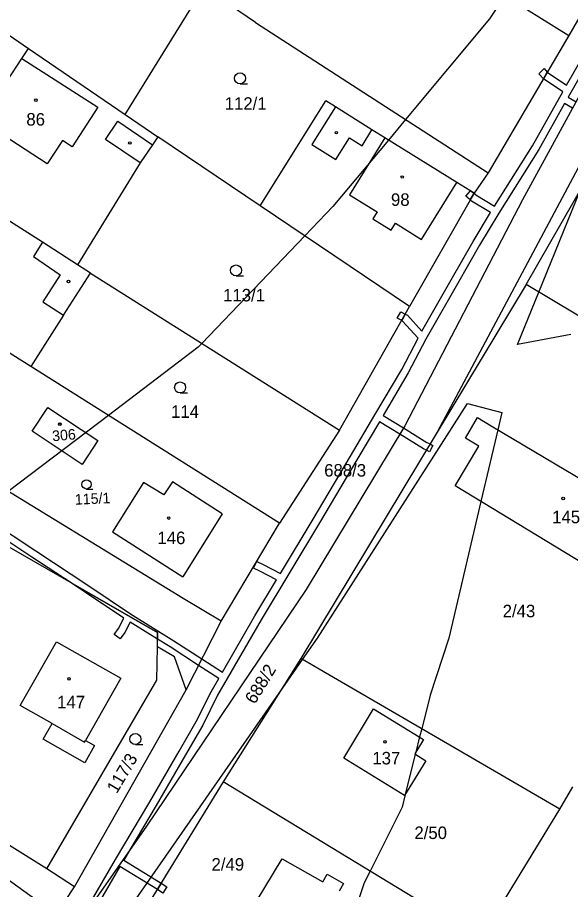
# Model space of a CAD drawing. Extents: x -747333 to -745433, y -1133152 to -1130600.
# Drawn here: x -746266.8 to -746191.7, y -1131861.6 to -1131743.1 of the extents above; entities that cross this region are included whole.
import ezdxf

# ---------------------------------------------------------------- set-up
doc = ezdxf.new("R2010")
doc.units = 0
for name, color, linetype in [('Vrstva 1', 7, 'Continuous'), ('Vrstva 18', 7, 'Continuous'), ('Vrstva 19', 7, 'Continuous'), ('Vrstva 25', 7, 'Continuous'), ('Vrstva 3', 7, 'Continuous'), ('Vrstva 30', 7, 'Continuous'), ('Vrstva 37', 7, 'Continuous'), ('Vrstva 4', 7, 'Continuous'), ('Vrstva 52', 7, 'Continuous'), ('Vrstva 6', 7, 'Continuous')]:
    doc.layers.add(name, color=color, linetype=linetype)

msp = doc.modelspace()

# ---------------------------------------------------------------- linework, layer by layer
at = {"layer": 'Vrstva 1'}
for p, q in [((-746264.81, -1131799.25), (-746262.65, -1131796.05)), ((-746262.65, -1131796.05), (-746255.85, -1131800.56)), ((-746257.99, -1131803.78), (-746264.81, -1131799.25)), ((-746255.85, -1131800.56), (-746257.99, -1131803.78)), ((-746277.66, -1131853.3), (-746261.5, -1131864.88))]:
    msp.add_line(p, q, dxfattribs=at)
for points in [[(-746220.28, -1131727.78), (-746191.89, -1131745.5)], [(-746183.97, -1131731.72), (-746191.89, -1131745.5)], [(-746234.47, -1131743.75), (-746241.4, -1131739.01)], [(-746252.15, -1131756.25), (-746243.25, -1131741.86)], [(-746234.47, -1131743.75), (-746202.88, -1131764.19)], [(-746270.15, -1131743.99), (-746265.3, -1131747.29)], [(-746191.89, -1131745.5), (-746202.88, -1131764.19)], [(-746266.18, -1131748.62), (-746265.3, -1131747.29)], [(-746265.3, -1131747.29), (-746252.15, -1131756.25)], [(-746271.78, -1131757.1), (-746266.18, -1131748.62)], [(-746197.7, -1131779.34), (-746181.5, -1131751.09)], [(-746233.81, -1131768.65), (-746224.93, -1131754.39)], [(-746223.6, -1131755.22), (-746224.93, -1131754.39)], [(-746218.64, -1131758.31), (-746223.6, -1131755.22)], [(-746252.15, -1131756.25), (-746247.71, -1131759.28)], [(-746216.88, -1131759.41), (-746218.64, -1131758.31)], [(-746248.44, -1131760.35), (-746250.13, -1131762.83)], [(-746247.71, -1131759.28), (-746248.44, -1131760.35)], [(-746233.81, -1131768.65), (-746247.71, -1131759.28)], [(-746207.1, -1131765.49), (-746216.88, -1131759.41)], [(-746263.38, -1131773.61), (-746281.7, -1131761.93)], [(-746250.13, -1131762.83), (-746258.62, -1131776.67)], [(-746202.88, -1131764.19), (-746204.77, -1131766.94)], [(-746204.77, -1131766.94), (-746207.1, -1131765.49)], [(-746204.77, -1131766.94), (-746213.53, -1131782.34)], [(-746213.53, -1131782.34), (-746233.81, -1131768.65)], [(-746258.62, -1131776.67), (-746263.38, -1131773.61)], [(-746256.85, -1131777.8), (-746258.62, -1131776.67)], [(-746260.53, -1131783.53), (-746256.85, -1131777.8)], [(-746256.85, -1131777.8), (-746223.05, -1131799.15)], [(-746197.7, -1131779.34), (-746209.77, -1131799.39)], [(-746163.29, -1131799.92), (-746197.7, -1131779.34)], [(-746223.05, -1131799.15), (-746213.53, -1131782.34)], [(-746260.53, -1131783.53), (-746264.99, -1131790.48)], [(-746264.99, -1131790.48), (-746269.53, -1131787.61)], [(-746231.2, -1131811.77), (-746264.99, -1131790.48)], [(-746205.95, -1131800.2), (-746204.31, -1131797.43)], [(-746204.31, -1131797.43), (-746202.46, -1131798.53)], [(-746223.05, -1131799.15), (-746231.2, -1131811.77)], [(-746209.77, -1131799.39), (-746228.3, -1131830.15)], [(-746202.46, -1131798.53), (-746182.41, -1131810.46)], [(-746204.11, -1131801.3), (-746205.95, -1131800.2)], [(-746207.33, -1131806.71), (-746204.11, -1131801.3)], [(-746244.27, -1131822.03), (-746274.35, -1131803.63)], [(-746249.68, -1131806.24), (-746253.9, -1131812.96)], [(-746246.91, -1131807.93), (-746249.68, -1131806.24)], [(-746245.72, -1131806.17), (-746246.91, -1131807.93)], [(-746238.97, -1131810.51), (-746245.72, -1131806.17)], [(-746182.44, -1131821.82), (-746207.33, -1131806.71)], [(-746238.97, -1131810.51), (-746244.34, -1131819.07)], [(-746239.12, -1131825.11), (-746231.2, -1131811.77)], [(-746247.77, -1131826.64), (-746271.26, -1131813.15)], [(-746253.9, -1131812.96), (-746244.34, -1131819.07)], [(-746239.12, -1131825.11), (-746244.27, -1131822.03)], [(-746243.86, -1131834.4), (-746239.12, -1131825.11)], [(-746247.79, -1131828.59), (-746247.77, -1131826.64)], [(-746266.42, -1131836.53), (-746261.49, -1131827.9)], [(-746261.49, -1131827.9), (-746252.77, -1131832.83)], [(-746247.85, -1131833.09), (-746247.79, -1131828.59)], [(-746245.47, -1131829.94), (-746247.79, -1131828.59)], [(-746243.86, -1131834.4), (-746245.47, -1131829.94)], [(-746228.3, -1131830.15), (-746238.83, -1131846.91)], [(-746193.13, -1131850.62), (-746228.3, -1131830.15)], [(-746262.8, -1131858.73), (-746247.85, -1131833.09)], [(-746252.77, -1131832.83), (-746257.55, -1131841.31)], [(-746259.04, -1131861.19), (-746243.86, -1131834.4)], [(-746262.09, -1131839.01), (-746266.42, -1131836.53)], [(-746222.48, -1131843.71), (-746218.42, -1131836.98)], [(-746218.42, -1131836.98), (-746211.63, -1131841.15)], [(-746263.3, -1131841.12), (-746262.09, -1131839.01)], [(-746257.66, -1131844.34), (-746263.3, -1131841.12)], [(-746256.34, -1131841.99), (-746257.66, -1131844.34)], [(-746257.55, -1131841.31), (-746256.34, -1131841.99)], [(-746211.63, -1131841.15), (-746212.84, -1131843.13)], [(-746262.8, -1131858.73), (-746289.03, -1131842.41)], [(-746212.84, -1131843.13), (-746211.33, -1131844.06)], [(-746214.22, -1131848.78), (-746222.48, -1131843.71)], [(-746211.33, -1131844.06), (-746214.22, -1131848.78)], [(-746238.83, -1131846.91), (-746249.25, -1131863.91)], [(-746203.84, -1131868.19), (-746238.83, -1131846.91)], [(-746193.13, -1131850.62), (-746191.35, -1131847.6)], [(-746200.63, -1131862.93), (-746193.13, -1131850.62)], [(-746235.4, -1131864.95), (-746230.84, -1131857.37)], [(-746230.84, -1131857.37), (-746225.31, -1131860.52)], [(-746259.04, -1131861.19), (-746262.8, -1131858.73)], [(-746225.31, -1131860.52), (-746224.72, -1131859.48)], [(-746224.72, -1131859.48), (-746222.52, -1131860.73)], [(-746222.52, -1131860.73), (-746223.11, -1131861.77)], [(-746261.5, -1131864.88), (-746259.04, -1131861.19)]]:
    msp.add_lwpolyline(points, dxfattribs=at)
at = {"layer": 'Vrstva 25'}
for p, q in [((-746236.56, -1131752.07), (-746235.56, -1131752.07)), ((-746237.1, -1131778.18), (-746236.1, -1131778.18)), ((-746244.7, -1131794.08), (-746243.7, -1131794.08)), ((-746257.41, -1131807.13), (-746256.57, -1131807.13)), ((-746250.77, -1131841.85), (-746249.77, -1131841.85))]:
    msp.add_line(p, q, dxfattribs=at)
for centre, radius in [((-746236.56, -1131751.32), 0.75), ((-746264.28, -1131754.29), 0.174503), ((-746223.48, -1131758.71), 0.174503), ((-746251.52, -1131760.11), 0.174503), ((-746214.53, -1131764.74), 0.174503), ((-746237.1, -1131777.43), 0.75), ((-746259.86, -1131778.93), 0.174503), ((-746244.7, -1131793.33), 0.75), ((-746261.03, -1131798.31), 0.146582), ((-746257.41, -1131806.5), 0.63), ((-746192.67, -1131808.42), 0.174503), ((-746246.25, -1131811.08), 0.174503), ((-746259.79, -1131832.93), 0.174503), ((-746250.77, -1131841.1), 0.75), ((-746216.88, -1131841.48), 0.174503)]:
    msp.add_circle(centre, radius, dxfattribs=at)
at = {"layer": 'Vrstva 3'}
for points in [[(-746271.78, -1131757.1), (-746266.18, -1131748.62)], [(-746266.18, -1131748.62), (-746255.89, -1131755.27)], [(-746255.89, -1131755.27), (-746259.35, -1131760.63)], [(-746262.74, -1131762.94), (-746271.78, -1131757.1)], [(-746260.69, -1131759.76), (-746262.74, -1131762.94)], [(-746259.35, -1131760.63), (-746260.69, -1131759.76)], [(-746216.88, -1131759.41), (-746221.71, -1131767.14)], [(-746207.1, -1131765.49), (-746216.88, -1131759.41)], [(-746211.93, -1131773.21), (-746207.1, -1131765.49)], [(-746221.71, -1131767.14), (-746217.93, -1131769.49)], [(-746217.93, -1131769.49), (-746218.51, -1131770.42)], [(-746218.51, -1131770.42), (-746216.05, -1131771.94)], [(-746216.05, -1131771.94), (-746215.47, -1131771.01)], [(-746215.47, -1131771.01), (-746211.93, -1131773.21)], [(-746264.81, -1131799.25), (-746262.65, -1131796.05)], [(-746262.65, -1131796.05), (-746255.85, -1131800.56)], [(-746205.95, -1131800.2), (-746204.31, -1131797.43)], [(-746204.31, -1131797.43), (-746202.46, -1131798.53)], [(-746257.99, -1131803.78), (-746264.81, -1131799.25)], [(-746202.46, -1131798.53), (-746182.41, -1131810.46)], [(-746255.85, -1131800.56), (-746257.99, -1131803.78)], [(-746204.11, -1131801.3), (-746205.95, -1131800.2)], [(-746207.33, -1131806.71), (-746204.11, -1131801.3)], [(-746249.68, -1131806.24), (-746253.9, -1131812.96)], [(-746246.91, -1131807.93), (-746249.68, -1131806.24)], [(-746245.72, -1131806.17), (-746246.91, -1131807.93)], [(-746238.97, -1131810.51), (-746245.72, -1131806.17)], [(-746182.44, -1131821.82), (-746207.33, -1131806.71)], [(-746238.97, -1131810.51), (-746244.34, -1131819.07)], [(-746253.9, -1131812.96), (-746244.34, -1131819.07)], [(-746266.42, -1131836.53), (-746261.49, -1131827.9)], [(-746261.49, -1131827.9), (-746252.77, -1131832.83)], [(-746252.77, -1131832.83), (-746257.55, -1131841.31)], [(-746262.09, -1131839.01), (-746266.42, -1131836.53)], [(-746222.48, -1131843.71), (-746218.42, -1131836.98)], [(-746218.42, -1131836.98), (-746211.63, -1131841.15)], [(-746262.09, -1131839.01), (-746257.67, -1131841.53)], [(-746257.67, -1131841.53), (-746257.55, -1131841.31)], [(-746211.63, -1131841.15), (-746212.84, -1131843.13)], [(-746212.84, -1131843.13), (-746211.33, -1131844.06)], [(-746214.22, -1131848.78), (-746222.48, -1131843.71)], [(-746211.33, -1131844.06), (-746214.22, -1131848.78)], [(-746235.4, -1131864.95), (-746230.84, -1131857.37)], [(-746230.84, -1131857.37), (-746225.31, -1131860.52)], [(-746225.31, -1131860.52), (-746224.72, -1131859.48)], [(-746224.72, -1131859.48), (-746222.52, -1131860.73)], [(-746222.52, -1131860.73), (-746223.11, -1131861.77)]]:
    msp.add_lwpolyline(points, dxfattribs=at)
at = {"layer": 'Vrstva 30'}
for points in [[(-746192.22, -1131752.28), (-746188.55, -1131745.87)], [(-746187.69, -1131746.39), (-746192, -1131753.89)], [(-746195.98, -1131750.7), (-746195.25, -1131750.01)], [(-746195.35, -1131751.38), (-746195.98, -1131750.7)], [(-746195.35, -1131751.38), (-746194.83, -1131750.5)], [(-746194.83, -1131750.5), (-746195.35, -1131751.38)], [(-746195.25, -1131750.01), (-746194.83, -1131750.5)], [(-746194.83, -1131750.5), (-746192.22, -1131752.28)], [(-746192.72, -1131753.15), (-746195.35, -1131751.38)], [(-746196.83, -1131760.49), (-746192.72, -1131753.15)], [(-746192, -1131753.89), (-746190.93, -1131754.51)], [(-746192.48, -1131754.76), (-746195.97, -1131760.99)], [(-746191.41, -1131755.39), (-746192.48, -1131754.76)], [(-746202, -1131768.72), (-746196.83, -1131760.49)], [(-746195.97, -1131760.99), (-746201.41, -1131769.66)], [(-746205.89, -1131767.35), (-746205.27, -1131766.63)], [(-746205.29, -1131767.85), (-746205.89, -1131767.35)], [(-746205.29, -1131767.85), (-746204.77, -1131766.94)], [(-746204.77, -1131766.94), (-746205.29, -1131767.85)], [(-746205.27, -1131766.63), (-746204.77, -1131766.94)], [(-746204.77, -1131766.94), (-746204.53, -1131767.18)], [(-746204.53, -1131767.18), (-746202, -1131768.72)], [(-746205.11, -1131768), (-746205.29, -1131767.85)], [(-746202.53, -1131769.57), (-746205.11, -1131768)], [(-746204.88, -1131773.51), (-746202.53, -1131769.57)], [(-746201.41, -1131769.66), (-746204.02, -1131774.02)], [(-746207.9, -1131778.73), (-746204.88, -1131773.51)], [(-746204.02, -1131774.02), (-746207.04, -1131779.23)], [(-746211.87, -1131785.7), (-746207.9, -1131778.73)], [(-746207.04, -1131779.23), (-746211.35, -1131786.79)], [(-746215.2, -1131783.93), (-746214.71, -1131783.05)], [(-746214.61, -1131784.25), (-746215.2, -1131783.93)], [(-746214.71, -1131783.05), (-746214.12, -1131783.38)], [(-746214.61, -1131784.25), (-746214.12, -1131783.38)], [(-746214.12, -1131783.38), (-746214.61, -1131784.25)], [(-746214.12, -1131783.38), (-746213.84, -1131783.53)], [(-746213.84, -1131783.53), (-746211.87, -1131785.7)], [(-746214.48, -1131784.33), (-746214.61, -1131784.25)], [(-746212.39, -1131786.63), (-746214.48, -1131784.33)], [(-746214.61, -1131790.87), (-746212.39, -1131786.63)], [(-746211.35, -1131786.79), (-746213.74, -1131791.36)], [(-746218.24, -1131797.05), (-746214.61, -1131790.87)], [(-746213.74, -1131791.36), (-746217.13, -1131797.13)], [(-746221.55, -1131802.67), (-746218.24, -1131797.05)], [(-746217.64, -1131797.99), (-746220.69, -1131803.17)], [(-746214.86, -1131799.69), (-746217.64, -1131797.99)], [(-746217.13, -1131797.13), (-746214.35, -1131798.84)], [(-746214.35, -1131798.84), (-746211.17, -1131800.79)], [(-746211.66, -1131801.66), (-746214.86, -1131799.69)], [(-746211.26, -1131801.86), (-746211.66, -1131801.66)], [(-746211.17, -1131800.79), (-746210.74, -1131801.01)], [(-746210.36, -1131801.2), (-746210.81, -1131802.09)], [(-746210.74, -1131801.01), (-746210.36, -1131801.2)], [(-746226.63, -1131811.21), (-746221.55, -1131802.67)], [(-746210.81, -1131802.09), (-746211.26, -1131801.86)], [(-746220.69, -1131803.17), (-746225.77, -1131811.73)], [(-746231.08, -1131818.6), (-746226.63, -1131811.21)], [(-746264.84, -1131816.38), (-746270.74, -1131812.49)], [(-746270.61, -1131811.38), (-746264.3, -1131815.54)], [(-746225.77, -1131811.73), (-746233.7, -1131824.89)], [(-746264.3, -1131815.54), (-746257.11, -1131820.27)], [(-746259.35, -1131819.99), (-746264.84, -1131816.38)], [(-746234.71, -1131817.89), (-746234.29, -1131816.98)], [(-746234.29, -1131816.98), (-746233.41, -1131817.38)], [(-746233.85, -1131818.28), (-746234.71, -1131817.89)], [(-746231.59, -1131819.46), (-746233.85, -1131818.28)], [(-746233.41, -1131817.38), (-746231.08, -1131818.6)], [(-746234.56, -1131824.38), (-746231.59, -1131819.46)], [(-746247.77, -1131826.64), (-746259.35, -1131819.99)], [(-746257.67, -1131821.1), (-746259.35, -1131819.99)], [(-746259.35, -1131819.99), (-746247.77, -1131826.64)], [(-746257.11, -1131820.27), (-746251.42, -1131824.11)], [(-746252.34, -1131824.69), (-746257.67, -1131821.1)], [(-746251.42, -1131824.11), (-746245.53, -1131827.75)], [(-746253.07, -1131826.1), (-746252.34, -1131824.69)], [(-746251.49, -1131825.24), (-746252.21, -1131826.63)], [(-746247.78, -1131827.53), (-746251.49, -1131825.24)], [(-746233.7, -1131824.89), (-746239.61, -1131835.16)], [(-746238.95, -1131832.02), (-746234.56, -1131824.38)], [(-746253.64, -1131826.91), (-746253.07, -1131826.1)], [(-746252.21, -1131826.63), (-746252.83, -1131827.49)], [(-746247.78, -1131827.53), (-746247.77, -1131826.64)], [(-746247.77, -1131826.64), (-746247.78, -1131827.53)], [(-746252.83, -1131827.49), (-746253.64, -1131826.91)], [(-746246.05, -1131828.59), (-746247.78, -1131827.53)], [(-746245.53, -1131827.75), (-746241.73, -1131830.22)], [(-746242.18, -1131831.12), (-746246.05, -1131828.59)], [(-746241.73, -1131830.22), (-746238.95, -1131832.02)], [(-746239.45, -1131832.88), (-746242.18, -1131831.12)], [(-746240.49, -1131834.7), (-746239.45, -1131832.88)], [(-746242.51, -1131838.73), (-746240.49, -1131834.7)], [(-746239.61, -1131835.16), (-746241.63, -1131839.21)], [(-746244.82, -1131842.77), (-746242.51, -1131838.73)], [(-746241.63, -1131839.21), (-746243.96, -1131843.27)], [(-746248.81, -1131849.62), (-746244.82, -1131842.77)], [(-746243.96, -1131843.27), (-746247.95, -1131850.12)], [(-746253.47, -1131857.48), (-746248.81, -1131849.62)], [(-746247.95, -1131850.12), (-746251.52, -1131856.14)], [(-746251.52, -1131856.14), (-746252.36, -1131857.56)], [(-746257.53, -1131864.48), (-746253.47, -1131857.48)], [(-746252.87, -1131858.42), (-746256.67, -1131865)], [(-746247.79, -1131861.54), (-746252.87, -1131858.42)], [(-746252.36, -1131857.56), (-746247.27, -1131860.68)], [(-746247.27, -1131860.68), (-746247.79, -1131861.54)], [(-746247.79, -1131861.54), (-746247.27, -1131860.68)], [(-746247.27, -1131860.68), (-746246.49, -1131861.19)], [(-746247.04, -1131862.03), (-746247.79, -1131861.54)], [(-746246.49, -1131861.19), (-746247.04, -1131862.03)]]:
    msp.add_lwpolyline(points, dxfattribs=at)
at = {"layer": 'Vrstva 37'}
for centre in [(-746264.28, -1131754.29), (-746214.53, -1131764.74), (-746261.03, -1131798.31), (-746192.67, -1131808.42), (-746246.25, -1131811.08), (-746259.79, -1131832.93), (-746216.88, -1131841.48)]:
    msp.add_circle(centre, 0.174503, dxfattribs=at)
at = {"layer": 'Vrstva 4'}
for points in [[(-746266.18, -1131748.62), (-746255.89, -1131755.27)], [(-746255.89, -1131755.27), (-746259.35, -1131760.63)], [(-746223.6, -1131755.22), (-746226.83, -1131760.34)], [(-746262.74, -1131762.94), (-746271.78, -1131757.1)], [(-746254.84, -1131759.62), (-746253.15, -1131757.14)], [(-746253.15, -1131757.14), (-746248.44, -1131760.35)], [(-746219.99, -1131760.48), (-746218.64, -1131758.31)], [(-746260.69, -1131759.76), (-746262.74, -1131762.94)], [(-746259.35, -1131760.63), (-746260.69, -1131759.76)], [(-746250.13, -1131762.83), (-746254.84, -1131759.62)], [(-746226.83, -1131760.34), (-746223.56, -1131762.38)], [(-746223.56, -1131762.38), (-746221.68, -1131759.43)], [(-746216.88, -1131759.41), (-746221.71, -1131767.14)], [(-746221.68, -1131759.43), (-746219.99, -1131760.48)], [(-746211.93, -1131773.21), (-746207.1, -1131765.49)], [(-746221.71, -1131767.14), (-746217.93, -1131769.49)], [(-746217.93, -1131769.49), (-746218.51, -1131770.42)], [(-746218.51, -1131770.42), (-746216.05, -1131771.94)], [(-746216.05, -1131771.94), (-746215.47, -1131771.01)], [(-746215.47, -1131771.01), (-746211.93, -1131773.21)], [(-746263.38, -1131773.61), (-746264.62, -1131775.55)], [(-746264.62, -1131775.55), (-746260.97, -1131778.01)], [(-746260.97, -1131778.01), (-746263.35, -1131781.72)], [(-746263.35, -1131781.72), (-746260.53, -1131783.53)], [(-746262.09, -1131839.01), (-746257.67, -1131841.53)], [(-746257.67, -1131841.53), (-746257.55, -1131841.31)]]:
    msp.add_lwpolyline(points, dxfattribs=at)
at = {"layer": 'Vrstva 52'}
for points in [[(-746191.62, -1131786.12), (-746198.87, -1131787.5), (-746195.98, -1131780.37), (-746190.37, -1131766.55), (-746184.18, -1131751.31), (-746184, -1131750.88), (-746183.66, -1131750.33), (-746146.96, -1131691.87), (-746144.38, -1131687.76), (-746141, -1131682.38), (-746131.25, -1131666.25), (-746128.68, -1131663.08), (-746125.69, -1131659.37), (-746111.15, -1131655.31), (-746094.81, -1131650.75), (-746098.31, -1131653.98)], [(-746182.85, -1131713.12), (-746191.76, -1131726.65), (-746194.47, -1131730.77), (-746199.03, -1131737.69), (-746200.59, -1131740.07), (-746202.69, -1131743.25), (-746214.09, -1131756.94), (-746216.4, -1131759.71), (-746223.94, -1131768.75), (-746227.76, -1131772.74), (-746241.74, -1131787.34), (-746242.25, -1131787.88), (-746254.44, -1131797.13), (-746268.07, -1131807.47), (-746270.75, -1131809.5)], [(-746258, -1131873.37), (-746231.26, -1131834.87), (-746228.08, -1131830.28), (-746226.06, -1131827.38), (-746205.69, -1131795.5), (-746201, -1131796.75), (-746201.55, -1131799.07), (-746203.84, -1131808.83), (-746208.19, -1131827.38), (-746210.75, -1131835.13), (-746211.89, -1131839.7), (-746212.17, -1131840.82), (-746212.69, -1131842.88), (-746212.76, -1131843.18), (-746214.12, -1131848.62), (-746214.56, -1131850.37), (-746218.89, -1131859.04), (-746219.69, -1131860.63), (-746220.56, -1131863.22)]]:
    msp.add_lwpolyline(points, dxfattribs=at)
at = {"layer": 'Vrstva 6'}
for points in [[(-746175.35, -1131725.88), (-746198.19, -1131767.85)], [(-746188.47, -1131759.43), (-746209.77, -1131799.39)], [(-746198.19, -1131767.85), (-746214.17, -1131798.54)], [(-746214.17, -1131798.54), (-746227.58, -1131820.8)], [(-746227.58, -1131820.8), (-746249.27, -1131852.92)], [(-746249.27, -1131852.92), (-746268.11, -1131879.9)]]:
    msp.add_lwpolyline(points, dxfattribs=at)

# ---------------------------------------------------------------- texts
at = {"layer": 'Vrstva 18'}
for s, p in [('112/1', (-746238.64, -1131755.6)), ('113/1', (-746238.86, -1131781.64)), ('114', (-746245.93, -1131797.46)), ('688/3', (-746225.13, -1131805.44)), ('2/43', (-746200.89, -1131824.56)), ('2/50', (-746212.88, -1131854.69)), ('2/49', (-746240.43, -1131858.98))]:
    msp.add_text(s, height=1.7, dxfattribs=at).set_placement(p)
for s, height, rotation, p in [('115/1', 1.44, 2.57337, (-746258.96, -1131809.27)), ('688/2', 1.7, 58.39794, (-746234.56, -1131836.47)), ('117/3', 1.7, 59.3865, (-746253.3, -1131848.61))]:
    msp.add_text(s, height=height, rotation=rotation, dxfattribs=at).set_placement(p)
at = {"layer": 'Vrstva 19'}
for s, p in [('86', (-746265.58, -1131757.75)), ('98', (-746216.06, -1131768.66)), ('145', (-746194.17, -1131811.78)), ('146', (-746247.78, -1131814.62)), ('147', (-746261.4, -1131836.93)), ('137', (-746218.59, -1131844.55))]:
    msp.add_text(s, height=1.7, dxfattribs=at).set_placement(p)
msp.add_text('306', height=1.44, rotation=4.76361, dxfattribs=at).set_placement((-746262.015353, -1131800.649608))

doc.saveas('drawing.dxf')
